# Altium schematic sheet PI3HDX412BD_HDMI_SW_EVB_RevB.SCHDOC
size 386 x 246 mm
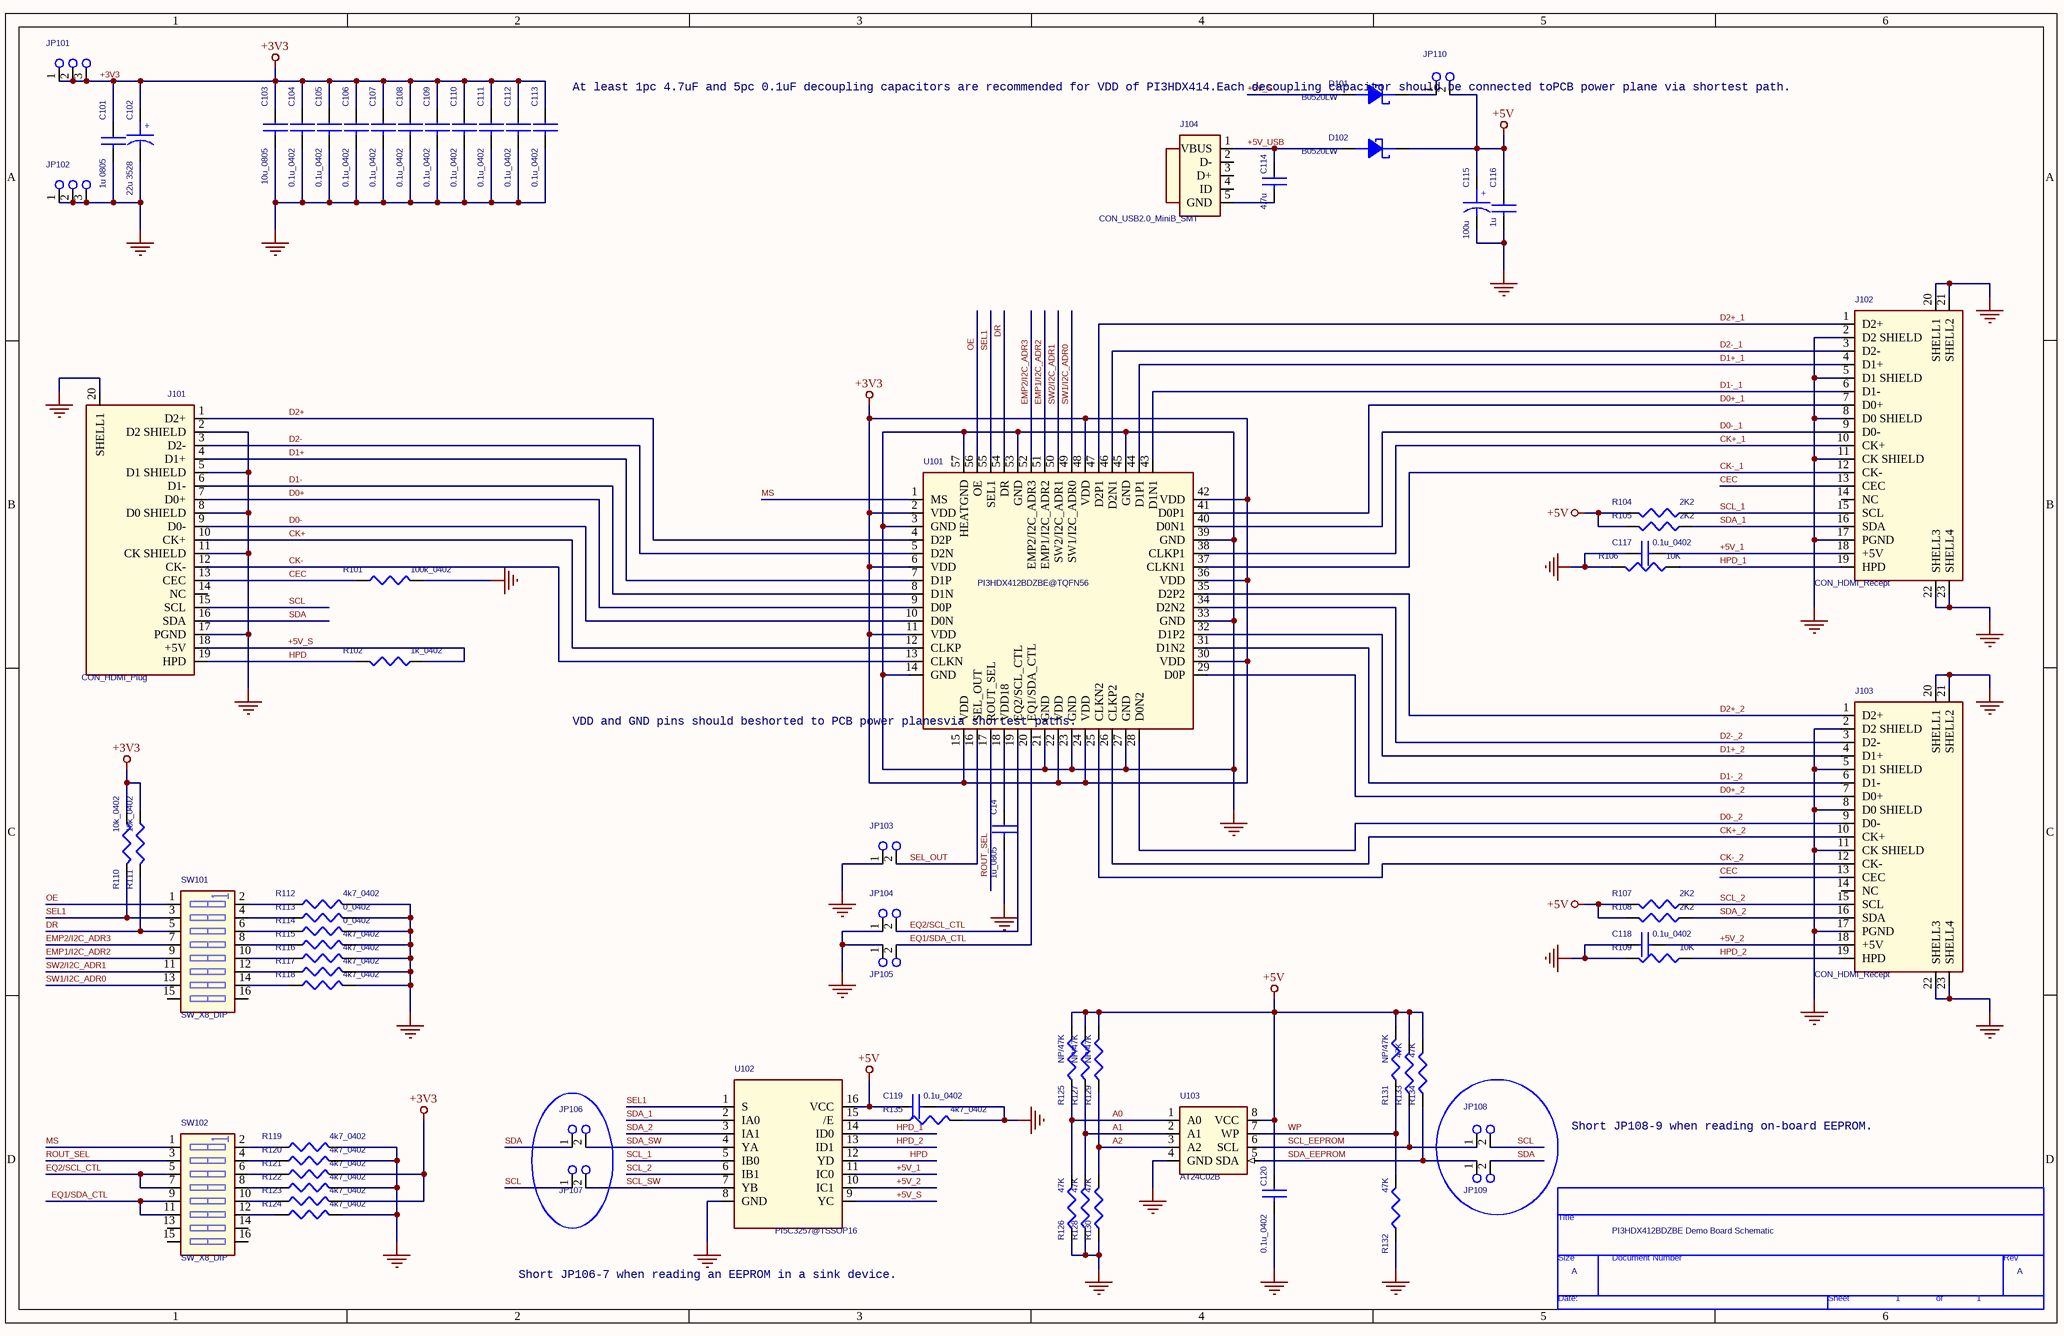
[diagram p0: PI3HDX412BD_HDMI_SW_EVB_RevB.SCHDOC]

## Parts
*  RevCode: A  Title: PI3HDX412BDZBE Demo Board Schematic  Page Number: 1  (hidden comment: TitleBlock0)  (graphical)
C14  1u_0805  [CC_0805]
C101  1u 0805  [CAP@CC_0805]
C102  22u 3528  [CAP@CT_3528]
C103  10u_0805  [CC_0805]
C104  0.1u_0402  [CC_0402]
C105  0.1u_0402  [CC_0402]
C106  0.1u_0402  [CC_0402]
C107  0.1u_0402  [CC_0402]
C108  0.1u_0402  [CC_0402]
C109  0.1u_0402  [CC_0402]
C110  0.1u_0402  [CC_0402]
C111  0.1u_0402  [CC_0402]
C112  0.1u_0402  [CC_0402]
C113  0.1u_0402  [CC_0402]
C114  4.7u  [CAP@CC_0805]
C115  100u  [CAP@CT_7343]
C116  1u  [CAP@CC_0805]
C117  0.1u_0402  [CC_0402]
C118  0.1u_0402  [CC_0402]
C119  0.1u_0402  [CC_0402]
C120  0.1u_0402  [CC_0402]
D101  B0520LW  [D@SOD-123]
D102  B0520LW  [D@SOD-123]
J101  CON_HDMI_Plug  [CON_HDMI_Plug]
J102  CON_HDMI_Recept  [CON_HDMI_Recept]
J103  CON_HDMI_Recept  [CON_HDMI_Recept]
J104  CON_USB2.0_MiniB_SMT  [CON_USB2.0_MiniB_SMT]
JP101  3x1 Pin Header  [3x1 Pin Header]  (value not drawn)
JP102  3x1 Pin Header  [3x1 Pin Header]  (value not drawn)
JP103  2x1 Pin Header  [2x1 Pin Header]  (value not drawn)
JP104  2x1 Pin Header  [2x1 Pin Header]  (value not drawn)
JP105  2x1 Pin Header  [2x1 Pin Header]  (value not drawn)
JP106  2x1 Pin Header  [2x1 Pin Header]  (value not drawn)
JP107  2x1 Pin Header  [2x1 Pin Header]  (value not drawn)
JP108  2x1 Pin Header  [2x1 Pin Header]  (value not drawn)
JP109  2x1 Pin Header  [2x1 Pin Header]  (value not drawn)
JP110  2x1 Pin Header  [2x1 Pin Header]  (value not drawn)
R101  100k_0402  [R_0402]
R102  1k_0402  [R_0402]
R104  2K2  [RES@R_0402]
R105  2K2  [RES@R_0402]
R106  10K  [RES@R_0402]
R107  2K2  [RES@R_0402]
R108  2K2  [RES@R_0402]
R109  10K  [RES@R_0402]
R110  10k_0402  [R_0402]
R111  10k_0402  [R_0402]
R112  4k7_0402  [R_0402]
R113  0_0402  [R_0402]
R114  0_0402  [R_0402]
R115  4k7_0402  [R_0402]
R116  4k7_0402  [R_0402]
R117  4k7_0402  [R_0402]
R118  4k7_0402  [R_0402]
R119  4k7_0402  [R_0402]
R120  4k7_0402  [R_0402]
R121  4k7_0402  [R_0402]
R122  4k7_0402  [R_0402]
R123  4k7_0402  [R_0402]
R124  4k7_0402  [R_0402]
R125  NP/47K  [RES@R_0402]
R126  47K  [RES@R_0402]
R127  NP/47K  [RES@R_0402]
R128  47K  [RES@R_0402]
R129  NP/47K  [RES@R_0402]
R130  47K  [RES@R_0402]
R131  NP/47K  [RES@R_0402]
R132  47K  [RES@R_0402]
R133  47K  [RES@R_0402]
R134  47K  [RES@R_0402]
R135  4k7_0402  [R_0402]
SW101  SW_X8_DIP  [SW_X8_DIP]
SW102  SW_X8_DIP  [SW_X8_DIP]
U101  PI3HDX412BDZBE@TQFN56  [TQFN56]
U102  PI5C3257@TSSOP16  [TSSOP20]
U103  AT24C02B  [SOIC8]

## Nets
+3V3: C101.1 C102.1 C103.1 C104.1 C105.1 C106.1 C107.1 C108.1 C109.1 C110.1 C111.1 C112.1 C113.1 JP101.1 JP101.2 JP101.3 R110.1 R111.1 R121.2 R123.2 U101.2(VDD) U101.6(VDD) U101.11(VDD) U101.15(VDD) U101.22(VDD) U101.24(VDD) U101.30(VDD) U101.36(VDD) U101.42(VDD) U101.48(VDD)
+5V: C115.1 C116.1 C119.1 C120.1 D102.CATHODE JP110.2 R104.2 R105.2 R107.2 R108.2 R125.2 R127.2 R129.2 R131.2 R133.2 R134.2 U102.16(VCC) U103.8(VCC)
GND: C14.2 C101.2 C102.2 C103.2 C104.2 C105.2 C106.2 C107.2 C108.2 C109.2 C110.2 C111.2 C112.2 C113.2 C115.2 C116.2 C117.1 C118.1 C119.2 C120.2 J101.2(D2_SHIELD) J101.5(D1_SHIELD) J101.8(D0_SHIELD) J101.11(CK_SHIELD) J101.17(PGND) J101.20(SHELL1) J102.2(D2_SHIELD) J102.5(D1_SHIELD) J102.8(D0_SHIELD) J102.11(CK_SHIELD) J102.17(PGND) J102.20(SHELL1) J102.21(SHELL2) J102.22(SHELL3) J102.23(SHELL4) J103.2(D2_SHIELD) J103.5(D1_SHIELD) J103.8(D0_SHIELD) J103.11(CK_SHIELD) J103.17(PGND) J103.20(SHELL1) J103.21(SHELL2) J103.22(SHELL3) J103.23(SHELL4) JP102.1 JP102.2 JP102.3 JP103.1 JP104.1 JP105.1 R101.2 R106.2 R109.2 R112.2 R113.2 R114.2 R115.2 R116.2 R117.2 R118.2 R119.2 R120.2 R122.2 R124.2 R126.1 R128.1 R130.1 R132.1 R135.2 U101.3(GND) U101.14(GND) U101.21(GND) U101.23(GND) U101.27(GND) U101.33(GND) U101.39(GND) U101.45(GND) U101.53(GND) U101.57(HEATGND) U102.8(GND) U103.4(GND)
+5V_1: C117.2 J102.18(+5V) U102.11(IC0)
+5V_2: C118.2 J103.18(+5V) U102.10(IC1)
+5V_S: D101.ANODE J101.18(+5V) R102.1 U102.9(YC)
+5V_USB: C114.1 D102.ANODE J104.1(VBUS)
A0: R125.1 R126.2 U103.1(A0)
A1: R127.1 R128.2 U103.2(A1)
A2: R129.1 R130.2 U103.3(A2)
CEC: J101.13(CEC) J102.13(CEC) J103.13(CEC) R101.1
CK+: J101.10(CK+) U101.12(CLKP)
CK+_1: J102.10(CK+) U101.38(CLKP1)
CK+_2: J103.10(CK+) U101.26(CLKP2)
CK-: J101.12(CK-) U101.13(CLKN)
CK-_1: J102.12(CK-) U101.37(CLKN1)
CK-_2: J103.12(CK-) U101.25(CLKN2)
D0+: J101.7(D0+) U101.9(D0P)
D0+_1: J102.7(D0+) U101.41(D0P1)
D0+_2: J103.7(D0+) U101.29(D0P)
D0-: J101.9(D0-) U101.10(D0N)
D0-_1: J102.9(D0-) U101.40(D0N1)
D0-_2: J103.9(D0-) U101.28(D0N2)
D1+: J101.4(D1+) U101.7(D1P)
D1+_1: J102.4(D1+) U101.44(D1P1)
D1+_2: J103.4(D1+) U101.32(D1P2)
D1-: J101.6(D1-) U101.8(D1N)
D1-_1: J102.6(D1-) U101.43(D1N1)
D1-_2: J103.6(D1-) U101.31(D1N2)
D2+: J101.1(D2+) U101.4(D2P)
D2+_1: J102.1(D2+) U101.47(D2P1)
D2+_2: J103.1(D2+) U101.35(D2P2)
D2-: J101.3(D2-) U101.5(D2N)
D2-_1: J102.3(D2-) U101.46(D2N1)
D2-_2: J103.3(D2-) U101.34(D2N2)
DR: R111.2 SW101.5(A3) U101.54(DR)
EMP1/I2C_ADR2: SW101.9(A5) U101.51(EMP1/I2C_ADR2)
EMP2/I2C_ADR3: SW101.7(A4) U101.52(EMP2/I2C_ADR3)
EQ1/SDA_CTL: JP105.2 SW102.9(A5) SW102.11(A6) U101.20(EQ1/SDA_CTL)
EQ2/SCL_CTL: JP104.2 SW102.5(A3) SW102.7(A4) U101.19(EQ2/SCL_CTL)
HPD: J101.19(HPD) R102.2 U102.12(YD)
HPD_1: J102.19(HPD) R106.1 U102.14(ID0)
HPD_2: J103.19(HPD) R109.1 U102.13(ID1)
MS: SW102.1(A1) U101.1(MS)
OE: SW101.1(A1) U101.56(OE)
ROUT_SEL: SW102.3(A2) U101.17(ROUT_SEL)
SCL: J101.15(SCL) JP107.1 JP108.2
SCL_1: J102.15(SCL) R104.1 U102.5(IB0)
SCL_2: J103.15(SCL) R107.1 U102.6(IB1)
SCL_EEPROM: JP108.1 R133.1 U103.6(SCL)
SCL_SW: JP107.2 U102.7(YB)
SDA: J101.16(SDA) JP106.1 JP109.2
SDA_1: J102.16(SDA) R105.1 U102.2(IA0)
SDA_2: J103.16(SDA) R108.1 U102.3(IA1)
SDA_EEPROM: JP109.1 R134.1 U103.5(SDA)
SDA_SW: JP106.2 U102.4(YA)
SEL1: R110.2 SW101.3(A2) U101.55(SEL1) U102.1(S)
SEL_OUT: JP103.2 U101.16(SEL_OUT)
SW1/I2C_ADR0: SW101.13(A7) U101.49(SW1/I2C_ADR0)
SW2/I2C_ADR1: SW101.11(A6) U101.50(SW2/I2C_ADR1)
WP: R131.1 R132.2 U103.7(WP)
NetC14_1: C14.1 U101.18(VDD18)
NetC114_2: C114.2 J104.5(GND)
NetD101_CATHODE: D101.CATHODE JP110.1
NetR112_1: R112.1 SW101.2(B1)
NetR113_1: R113.1 SW101.4(B2)
NetR114_1: R114.1 SW101.6(B3)
NetR115_1: R115.1 SW101.8(B4)
NetR116_1: R116.1 SW101.10(B5)
NetR117_1: R117.1 SW101.12(B6)
NetR118_1: R118.1 SW101.14(B7)
NetR119_1: R119.1 SW102.2(B1)
NetR120_1: R120.1 SW102.4(B2)
NetR121_1: R121.1 SW102.6(B3)
NetR122_1: R122.1 SW102.8(B4)
NetR123_1: R123.1 SW102.10(B5)
NetR124_1: R124.1 SW102.12(B6)
NetR135_1: R135.1 U102.15(/E)

Not connected (* = marked no-connect by the designer): J101 14(NC); J102 14(NC); J103 14(NC); J104 2(D-) 3(D+) 4(ID); SW101 15(A8) 16(B8); SW102 13(A7) 14(B7) 15(A8) 16(B8)

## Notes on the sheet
- At least 1pc 4.7uF and 5pc 0.1uF decoupling capacitors are recommended for VDD of PI3HDX414.Each decoupling capacitor should be connected toPCB power plane via shortest path.
- (near U101) VDD and GND pins should beshorted to PCB power planesvia shortest paths.
- Short JP108-9 when reading on-board EEPROM.
- Short JP106-7 when reading an EEPROM in a sink device.

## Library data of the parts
C14 = C_1.0u_0805
C101 C114 C116 = CHIP CAP0805
C102 = 22UF 3528
C103 = C_10u_0805
C104-C113 C117-C120 = C_0.1u_0402
C115 = 100UF 7343_1
D101 D102 = SchottkyDiode@SOD-123_1
JP103-JP107 = 2x1 Pin Header_Dup1
R101 R102 R110-R124 R135 = R_0402
R104-R109 R125-R134 = CHIP RES0402_0
U101 = PI3HDMI412AD@TQFN56_4
U102 = PI5C3244@TSSOP20_1
U103 = 24C02@SOIC8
